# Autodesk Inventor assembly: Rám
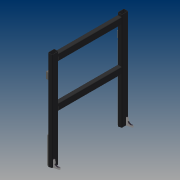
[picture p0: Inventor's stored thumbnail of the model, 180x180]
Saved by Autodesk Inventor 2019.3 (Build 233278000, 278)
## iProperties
Created: 2019-02
Part Number: Rám
Material: Všeobecné
Document SubType Name: Assembly
Designer: B-hon
Author: B-hon
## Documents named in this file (7)
- C:\Users\B-hon\OneDrive\Plocha\Bakalářka22\Rám\Rám.iam
- C:\Users\B-hon\OneDrive\Plocha\Bakalářka22\Rám\CSN 426936 - 60x40x3-1000.ipt
- C:\Users\B-hon\OneDrive\Plocha\Bakalářka22\Rám\CSN 426936 - 60x40x3-584.ipt
- C:\Users\B-hon\OneDrive\Plocha\Bakalářka22\Rám\25x6x850.ipt
- C:\Users\B-hon\OneDrive\Plocha\Bakalářka22\Rám\45x6x250.ipt
- C:\Users\B-hon\OneDrive\Plocha\Bakalářka22\Rám\Držák desky.ipt
- C:\Users\B-hon\OneDrive\Plocha\Bakalářka22\Opěrka.ipt
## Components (12 placed, 6 different names)
1. 45x6x250:1 — Proti sobě:4, Proti sobě:5, Stejný směr:4
2. 45x6x250:2 — Proti sobě:6, Proti sobě:7, Stejný směr:5
3. Držák desky:1 — Proti sobě:10, Stejný směr:12, Stejný směr:13
4. Držák desky:2 — Proti sobě:11, Stejný směr:10, Stejný směr:11
5. Opěrka:1 — Proti sobě:12, Stejný směr:14, Stejný směr:15
6. Opěrka:2 — Stejný směr:16, Proti sobě:13, Stejný směr:17
7. CSN 426936 - 60x40x3-1000:1 — Proti sobě:1, Stejný směr:1, Stejný směr:2, Proti sobě:2, Stejný směr:3, Proti sobě:3, Proti sobě:4, Proti sobě:10, Stejný směr:12, Stejný směr:13, Stejný směr:16, Proti sobě:13, Stejný směr:17
8. CSN 426936 - 60x40x3-1000:2 — Proti sobě:6, Proti sobě:11, Stejný směr:10, Stejný směr:11, Proti sobě:12, Stejný směr:14, Stejný směr:15
9. 25x6x850:1 — Proti sobě:2, Stejný směr:3, Proti sobě:3, Proti sobě:5, Stejný směr:4
10. 25x6x850:2 — Proti sobě:7, Stejný směr:5
11. CSN 426936 - 60x40x3-584:1 — Proti sobě:1, Stejný směr:1, Stejný směr:2
12. CSN 426936 - 60x40x3-584:2
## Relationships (24: Flush 13, Mate 11)
- Proti sobě:1 [Mate]: CSN 426936 - 60x40x3-1000:1 ↔ CSN 426936 - 60x40x3-584:1
- Stejný směr:1 [Flush]: CSN 426936 - 60x40x3-1000:1 ↔ CSN 426936 - 60x40x3-584:1
- Stejný směr:2 [Flush]: CSN 426936 - 60x40x3-1000:1 ↔ CSN 426936 - 60x40x3-584:1
- Proti sobě:2 [Mate]: CSN 426936 - 60x40x3-1000:1 ↔ 25x6x850:1
- Stejný směr:3 [Flush]: CSN 426936 - 60x40x3-1000:1 ↔ 25x6x850:1
- Proti sobě:3 [Mate]: CSN 426936 - 60x40x3-1000:1 ↔ 25x6x850:1
- Proti sobě:4 [Mate]: 45x6x250:1 ↔ CSN 426936 - 60x40x3-1000:1
- Proti sobě:5 [Mate]: 45x6x250:1 ↔ 25x6x850:1
- Stejný směr:4 [Flush]: 45x6x250:1 ↔ 25x6x850:1
- Proti sobě:6 [Mate]: 45x6x250:2 ↔ CSN 426936 - 60x40x3-1000:2
- Proti sobě:7 [Mate]: 45x6x250:2 ↔ 25x6x850:2
- Stejný směr:5 [Flush]: 45x6x250:2 ↔ 25x6x850:2
- Proti sobě:10 [Mate]: Držák desky:1 ↔ CSN 426936 - 60x40x3-1000:1
- Proti sobě:11 [Mate]: Držák desky:2 ↔ CSN 426936 - 60x40x3-1000:2
- Stejný směr:10 [Flush]: Držák desky:2 ↔ CSN 426936 - 60x40x3-1000:2
- Stejný směr:11 [Flush]: Držák desky:2 ↔ CSN 426936 - 60x40x3-1000:2
- Stejný směr:12 [Flush]: Držák desky:1 ↔ CSN 426936 - 60x40x3-1000:1
- Stejný směr:13 [Flush]: Držák desky:1 ↔ CSN 426936 - 60x40x3-1000:1
- Proti sobě:12 [Mate]: Opěrka:1 ↔ CSN 426936 - 60x40x3-1000:2
- Stejný směr:14 [Flush]: Opěrka:1 ↔ CSN 426936 - 60x40x3-1000:2
- Stejný směr:15 [Flush]: Opěrka:1 ↔ CSN 426936 - 60x40x3-1000:2
- Stejný směr:16 [Flush]: Opěrka:2 ↔ CSN 426936 - 60x40x3-1000:1
- Proti sobě:13 [Mate]: Opěrka:2 ↔ CSN 426936 - 60x40x3-1000:1
- Stejný směr:17 [Flush]: Opěrka:2 ↔ CSN 426936 - 60x40x3-1000:1
